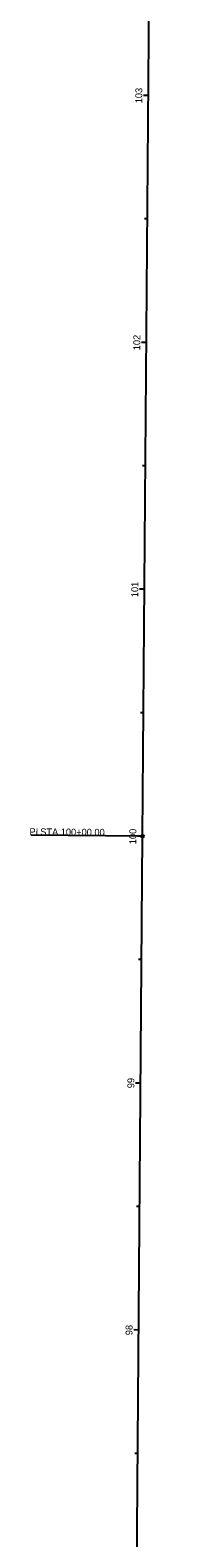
# Model space of a CAD drawing. Extents: x 217610 to 217676, y 457884 to 460293.
# Drawn here: x 217618 to 217675, y 458495 to 459106 of the extents above; entities that cross this region are included whole.
import ezdxf

# ---------------------------------------------------------------- set-up
doc = ezdxf.new("R2010")
doc.units = 0
for name, color, linetype in [('RW_X_CL', 7, 'Continuous'), ('RW_X_CL_100_Cardinal_Points', 7, 'Continuous'), ('RW_X_CL_100_Stations', 7, 'Continuous'), ('RW_X_CL_500_Cardinal_Points', 7, 'Continuous'), ('RW_X_CL_500_Stations', 7, 'Continuous')]:
    doc.layers.add(name, color=color, linetype=linetype)

msp = doc.modelspace()

# ---------------------------------------------------------------- linework, layer by layer
at = {"layer": 'RW_X_CL'}
for p, q in [((217663.13, 458779.17), (217675.43, 460289.35)), ((217656.36, 457884.99), (217663.13, 458779.17))]:
    msp.add_line(p, q, dxfattribs=at)
at = {"layer": 'RW_X_CL_100_Cardinal_Points'}
msp.add_line((217663.13, 458779.17), (217618.14, 458779.53), dxfattribs=at)
msp.add_circle((217663.13, 458779.17), 0.6, dxfattribs=at)
at = {"layer": 'RW_X_CL_100_Stations'}
for p, q in [((217665.58, 459079.16), (217663.58, 459079.17)), ((217665.17, 459029.16), (217663.97, 459029.17)), ((217664.76, 458979.16), (217662.76, 458979.18)), ((217664.35, 458929.16), (217663.15, 458929.17)), ((217663.95, 458879.16), (217661.95, 458879.18)), ((217663.54, 458829.16), (217662.34, 458829.17)), ((217663.13, 458779.17), (217661.13, 458779.18)), ((217662.76, 458729.17), (217661.56, 458729.18)), ((217662.38, 458679.17), (217660.38, 458679.18)), ((217662, 458629.17), (217660.8, 458629.18)), ((217661.62, 458579.17), (217659.62, 458579.19)), ((217661.24, 458529.17), (217660.04, 458529.18))]:
    msp.add_line(p, q, dxfattribs=at)
at = {"layer": 'RW_X_CL_500_Cardinal_Points'}
msp.add_line((217663.13, 458779.17), (217618.14, 458779.53), dxfattribs=at)
msp.add_circle((217663.13, 458779.17), 0.6, dxfattribs=at)
at = {"layer": 'RW_X_CL_500_Stations'}
for p, q in [((217665.58, 459079.16), (217664.38, 459079.17)), ((217664.76, 458979.16), (217663.56, 458979.17)), ((217663.95, 458879.16), (217662.75, 458879.17)), ((217663.13, 458779.17), (217661.13, 458779.18)), ((217662.38, 458679.17), (217661.18, 458679.18)), ((217661.62, 458579.17), (217660.42, 458579.18))]:
    msp.add_line(p, q, dxfattribs=at)

# ---------------------------------------------------------------- texts
at = {"layer": 'RW_X_CL_100_Cardinal_Points'}
for s, p in [('PI', (217617.44, 458779.58)), (' STA. ', (217620.76, 458779.55)), ('100+00.00', (217630.08, 458779.47))]:
    msp.add_text(s, height=2.8, rotation=359.53369, dxfattribs=at).set_placement(p)
at = {"layer": 'RW_X_CL_100_Stations'}
for s, rotation, p in [('103', 89.53369, (217663.05, 459075.98)), ('102', 89.53369, (217662.24, 458975.97)), ('101', 89.53369, (217661.42, 458875.96)), ('100', 89.53369, (217660.61, 458775.92)), ('99', 89.56567, (217659.86, 458677.08)), ('98', 89.56567, (217659.1, 458577.06))]:
    msp.add_text(s, height=2.8, rotation=rotation, dxfattribs=at).set_placement(p)
at = {"layer": 'RW_X_CL_500_Cardinal_Points'}
for s, p in [('PI', (217617.44, 458779.58)), (' STA. ', (217620.76, 458779.55)), ('100+00.00', (217630.08, 458779.47))]:
    msp.add_text(s, height=2.8, rotation=359.53369, dxfattribs=at).set_placement(p)
at = {"layer": 'RW_X_CL_500_Stations'}
msp.add_text('100', height=2.8, rotation=89.53369, dxfattribs=at).set_placement((217660.61, 458775.92))

doc.saveas('drawing.dxf')
